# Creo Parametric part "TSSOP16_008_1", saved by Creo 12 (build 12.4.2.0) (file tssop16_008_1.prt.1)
Units: Custom; MM, KILOGRAM, SECS

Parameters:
  PTC_WM_ITERATION = "0"
  PTC_WM_VERSION = "-.0"
  PTC_WM_LIFECYCLE_STATE = "In Work"
  PTC_WM_LIFECYCLE = "MO_CADDocument"
  PTC_WM_CREATED_BY = "Maximilian Roepper (Z0017RMS: MO)"
  PTC_WM_CREATED_ON = "18-Sep-26 11:36:42 AM"
  PTC_WM_MODIFIED_BY = "Maximilian Roepper (Z0017RMS: MO)"
  PTC_WM_MODIFIED_ON = "18-Sep-26 11:36:46 AM"
  PDMLINKNUMBER = "PDM000071454863"
  PTC_WM_NAME = "tssop16_008_1.prt"
  PTC_WM_NUMBER = "PDM000071454863"

Other parameters: WEIGHT, WEIGHT_FACTOR, WEIGHT_ADD, _MASS_TEMP, _DIFF_TEMP, MC_ERRORS, SUPPLIER

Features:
  1. coordinate system
  2. datum plane "PRT_YZ"
  3. datum plane "PRT_XY"
  4. datum plane "PRT_XZ"
  5. coordinate system
  6. datum axis
  7. datum axis
  8. datum axis
  9. coordinate system
  10. imported feature

Other named items: PRT, SIEMENS_MO, DRW_VIEW_ORG, PRT_X, PRT_Y, PRT_Z, CS0, ROUGH_GROB

Layers: 00_STD_CSYS-KSYS, 01_STD_PLANES-EBENEN, 02_STD_AXES-ACHSEN, 03_STD_CSYS-KSYS, 24_IMPORT_FEAT-IMPORT_KE

Surfaces: 14 plane, 8 cylinder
